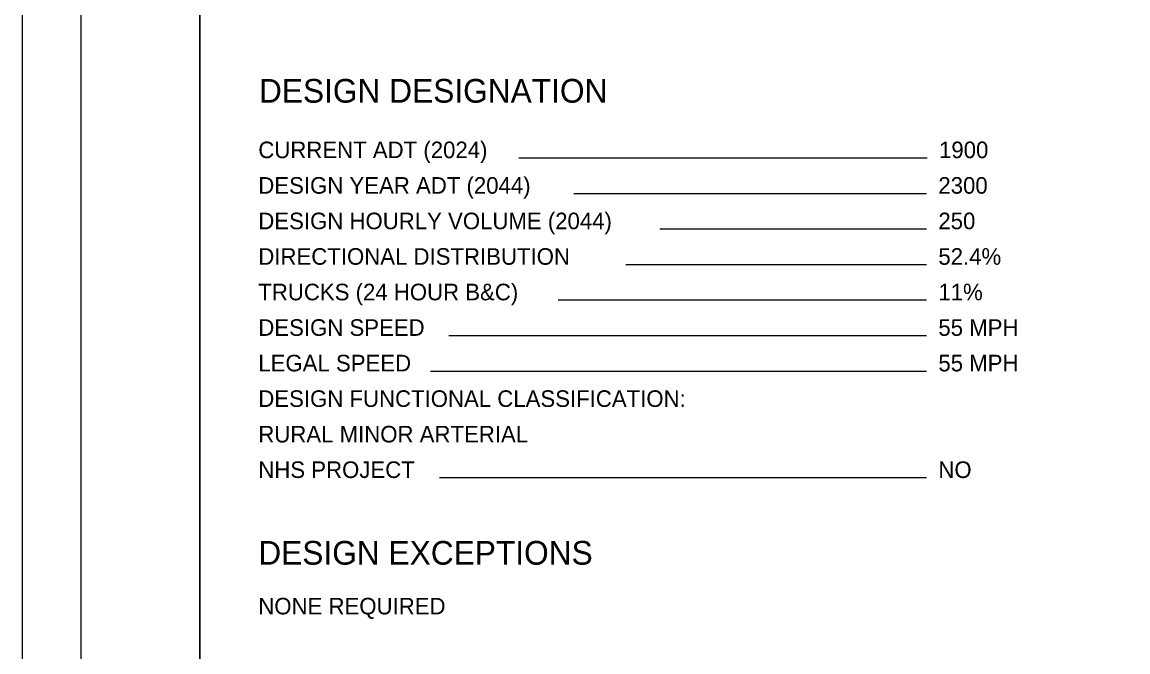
# Model space of a CAD drawing. Extents: x -8.2 to 34, y 0 to 22.
# Drawn here: x 0 to 9.34, y 5.64 to 10.95 of the extents above; entities that cross this region are included whole.
import ezdxf

# ---------------------------------------------------------------- set-up
doc = ezdxf.new("R2010")
doc.units = 0
for name, color, linetype in [('SH_Border', 7, 'Continuous'), ('SH_Cut_Line', 7, 'Continuous'), ('SH_Data', 7, 'Continuous'), ('SH_Text', 7, 'Continuous')]:
    doc.layers.add(name, color=color, linetype=linetype)

msp = doc.modelspace()

# ---------------------------------------------------------------- linework, layer by layer
at = {"layer": 'SH_Border'}
for points in [[(0.5, 21.5), (1.5, 21.5), (1.5, 0.5), (0.5, 0.5)], [(1.5, 21.5), (33.5, 21.5), (33.5, 0.5), (1.5, 0.5)]]:
    msp.add_lwpolyline(points, close=True, dxfattribs=at)
at = {"layer": 'SH_Cut_Line'}
msp.add_lwpolyline([(0, 0), (34, 0), (34, 22), (0, 22)], close=True, dxfattribs=at)
at = {"layer": 'SH_Data'}
for p, q in [((7.6424, 9.8062), (4.1936, 9.8062)), ((7.6368, 9.5062), (4.6592, 9.5062)), ((7.6368, 9.2062), (5.3852, 9.2062)), ((7.6368, 8.9062), (5.0988, 8.9062)), ((7.6368, 8.6062), (4.5259, 8.6062)), ((7.6368, 8.3062), (3.6035, 8.3062)), ((7.6368, 8.0062), (3.4488, 8.0062)), ((7.6368, 7.1062), (3.5243, 7.1062))]:
    msp.add_line(p, q, dxfattribs=at)

# ---------------------------------------------------------------- texts
msp.add_text('DESIGN DESIGNATION', height=0.2, dxfattribs=at).set_placement((2, 10.2747))
at = {"layer": 'SH_Text'}
for s, height, p in [('CURRENT ADT (2024)', 0.14, (1.9944, 9.8062)), ('1900', 0.14, (7.7424, 9.8062)), ('DESIGN YEAR ADT (2044)', 0.14, (1.9944, 9.5062)), ('2300', 0.14, (7.7368, 9.5062)), ('DESIGN HOURLY VOLUME (2044)', 0.14, (1.9944, 9.2062)), ('250', 0.14, (7.7368, 9.2062)), ('DIRECTIONAL DISTRIBUTION', 0.14, (1.9944, 8.9062)), ('52.4%', 0.14, (7.7368, 8.9062)), ('TRUCKS (24 HOUR B&C)', 0.14, (1.9944, 8.6062)), ('11%', 0.14, (7.7368, 8.6062)), ('DESIGN SPEED', 0.14, (1.9944, 8.3062)), ('55 MPH', 0.14, (7.7368, 8.3062)), ('LEGAL SPEED', 0.14, (1.9944, 8.0062)), ('55 MPH', 0.14, (7.7368, 8.0062)), ('DESIGN FUNCTIONAL CLASSIFICATION:', 0.14, (1.9944, 7.7062)), ('RURAL MINOR ARTERIAL', 0.14, (1.9944, 7.4062)), ('NHS PROJECT', 0.14, (1.9944, 7.1062)), ('NO', 0.14, (7.7368, 7.1062)), ('DESIGN EXCEPTIONS', 0.2, (1.9944, 6.3744)), ('NONE REQUIRED', 0.14, (1.9944, 5.9544))]:
    msp.add_text(s, height=height, dxfattribs=at).set_placement(p)

doc.saveas('drawing.dxf')
